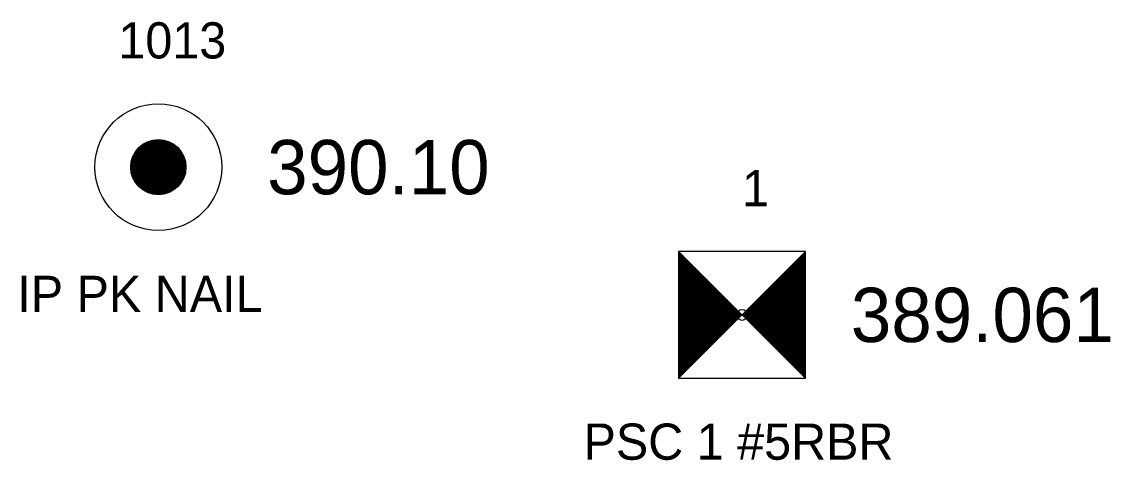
# Model space of a CAD drawing. Extents: x 2006517 to 2008868, y 1001613 to 1004633.
# Drawn here: x 2007086.65 to 2007116.66, y 1004406.67 to 1004418.78 of the extents above; entities that cross this region are included whole.
import ezdxf

# ---------------------------------------------------------------- set-up
doc = ezdxf.new("R2010")
doc.units = 0
for name, color, linetype in [('RD_EX_DV_Prop_txCode', 7, 'Continuous'), ('RD_EX_DV_PropPin', 7, 'Continuous'), ('RD_EX_TX_DV_Prop_ELEV', 7, 'Continuous'), ('RD_HC_Survey', 7, 'Continuous'), ('RD_HC_Survey_ELEV', 7, 'Continuous'), ('RD_HC_txCode', 7, 'Continuous'), ('RD_SMD_Locator', 7, 'Continuous')]:
    doc.layers.add(name, color=color, linetype=linetype)

msp = doc.modelspace()

# ---------------------------------------------------------------- linework, layer by layer
at = {"layer": 'RD_EX_DV_PropPin'}
for p, q in [((2007089.893, 1004414.215), (2007089.893, 1004415.317)), ((2007089.928, 1004414.184), (2007089.928, 1004415.348)), ((2007089.963, 1004414.156), (2007089.963, 1004415.376)), ((2007089.998, 1004414.131), (2007089.998, 1004415.4)), ((2007090.033, 1004414.11), (2007090.033, 1004415.422)), ((2007090.068, 1004414.09), (2007090.068, 1004415.442)), ((2007090.103, 1004414.073), (2007090.103, 1004415.459)), ((2007090.138, 1004414.058), (2007090.138, 1004415.473)), ((2007090.173, 1004414.045), (2007090.173, 1004415.486)), ((2007090.208, 1004414.034), (2007090.208, 1004415.497)), ((2007090.243, 1004414.025), (2007090.243, 1004415.507)), ((2007090.278, 1004414.018), (2007090.278, 1004415.514)), ((2007090.313, 1004414.012), (2007090.313, 1004415.52)), ((2007090.348, 1004414.008), (2007090.348, 1004415.524)), ((2007090.383, 1004414.006), (2007090.383, 1004415.526)), ((2007090.418, 1004414.005), (2007090.418, 1004415.527)), ((2007090.453, 1004414.006), (2007090.453, 1004415.526)), ((2007090.488, 1004414.008), (2007090.488, 1004415.524)), ((2007090.523, 1004414.012), (2007090.523, 1004415.52)), ((2007090.558, 1004414.018), (2007090.558, 1004415.514)), ((2007090.593, 1004414.025), (2007090.593, 1004415.507)), ((2007090.628, 1004414.034), (2007090.628, 1004415.497)), ((2007090.663, 1004414.045), (2007090.663, 1004415.486)), ((2007090.698, 1004414.058), (2007090.698, 1004415.473)), ((2007090.733, 1004414.073), (2007090.733, 1004415.459)), ((2007090.768, 1004414.09), (2007090.768, 1004415.442)), ((2007090.803, 1004414.11), (2007090.803, 1004415.422)), ((2007090.838, 1004414.131), (2007090.838, 1004415.4)), ((2007090.873, 1004414.156), (2007090.873, 1004415.376)), ((2007090.908, 1004414.184), (2007090.908, 1004415.348)), ((2007090.943, 1004414.215), (2007090.943, 1004415.317)), ((2007089.717, 1004414.468), (2007089.717, 1004415.064)), ((2007089.753, 1004414.396), (2007089.753, 1004415.135)), ((2007089.788, 1004414.339), (2007089.788, 1004415.192)), ((2007089.823, 1004414.292), (2007089.823, 1004415.24)), ((2007089.858, 1004414.251), (2007089.858, 1004415.281)), ((2007090.978, 1004414.251), (2007090.978, 1004415.281)), ((2007091.013, 1004414.292), (2007091.013, 1004415.24)), ((2007091.048, 1004414.339), (2007091.048, 1004415.192)), ((2007091.083, 1004414.396), (2007091.083, 1004415.135)), ((2007091.118, 1004414.468), (2007091.118, 1004415.064)), ((2007089.682, 1004414.57), (2007089.682, 1004414.962)), ((2007091.153, 1004414.57), (2007091.153, 1004414.962))]:
    msp.add_line(p, q, dxfattribs=at)
for radius in [1.75, 0.761]:
    msp.add_circle((2007090.418, 1004414.766), radius, dxfattribs=at)
at = {"layer": 'RD_HC_Survey'}
for p, q in [((2007104.762, 1004412.435), (2007108.261, 1004408.935)), ((2007108.261, 1004412.435), (2007104.762, 1004408.935)), ((2007104.786, 1004412.411), (2007104.786, 1004408.96)), ((2007104.811, 1004412.386), (2007104.811, 1004408.985)), ((2007104.836, 1004412.361), (2007104.836, 1004409.01)), ((2007104.861, 1004412.336), (2007104.861, 1004409.034)), ((2007104.885, 1004412.312), (2007104.885, 1004409.059)), ((2007108.138, 1004412.312), (2007108.138, 1004409.059)), ((2007108.162, 1004412.336), (2007108.162, 1004409.034)), ((2007108.187, 1004412.361), (2007108.187, 1004409.01)), ((2007108.212, 1004412.386), (2007108.212, 1004408.985)), ((2007108.237, 1004412.411), (2007108.237, 1004408.96)), ((2007104.91, 1004412.287), (2007104.91, 1004409.084)), ((2007104.935, 1004412.262), (2007104.935, 1004409.109)), ((2007104.959, 1004412.237), (2007104.959, 1004409.133)), ((2007104.984, 1004412.213), (2007104.984, 1004409.158)), ((2007105.009, 1004412.188), (2007105.009, 1004409.183)), ((2007105.034, 1004412.163), (2007105.034, 1004409.208)), ((2007105.058, 1004412.138), (2007105.058, 1004409.232)), ((2007105.083, 1004412.114), (2007105.083, 1004409.257)), ((2007105.108, 1004412.089), (2007105.108, 1004409.282)), ((2007105.133, 1004412.064), (2007105.133, 1004409.307)), ((2007105.157, 1004412.039), (2007105.157, 1004409.331)), ((2007105.182, 1004412.015), (2007105.182, 1004409.356)), ((2007107.841, 1004412.015), (2007107.841, 1004409.356)), ((2007107.866, 1004412.039), (2007107.866, 1004409.331)), ((2007107.89, 1004412.064), (2007107.89, 1004409.307)), ((2007107.915, 1004412.089), (2007107.915, 1004409.282)), ((2007107.94, 1004412.114), (2007107.94, 1004409.257)), ((2007107.965, 1004412.138), (2007107.965, 1004409.232)), ((2007107.989, 1004412.163), (2007107.989, 1004409.208)), ((2007108.014, 1004412.188), (2007108.014, 1004409.183)), ((2007108.039, 1004412.213), (2007108.039, 1004409.158)), ((2007108.064, 1004412.237), (2007108.064, 1004409.133)), ((2007108.088, 1004412.262), (2007108.088, 1004409.109)), ((2007108.113, 1004412.287), (2007108.113, 1004409.084)), ((2007105.207, 1004411.99), (2007105.207, 1004409.381)), ((2007105.232, 1004411.965), (2007105.232, 1004409.406)), ((2007105.256, 1004411.94), (2007105.256, 1004409.43)), ((2007105.281, 1004411.916), (2007105.281, 1004409.455)), ((2007105.306, 1004411.891), (2007105.306, 1004409.48)), ((2007105.331, 1004411.866), (2007105.331, 1004409.505)), ((2007105.355, 1004411.841), (2007105.355, 1004409.529)), ((2007105.38, 1004411.817), (2007105.38, 1004409.554)), ((2007105.405, 1004411.792), (2007105.405, 1004409.579)), ((2007105.43, 1004411.767), (2007105.43, 1004409.604)), ((2007105.454, 1004411.742), (2007105.454, 1004409.628)), ((2007105.479, 1004411.718), (2007105.479, 1004409.653)), ((2007105.504, 1004411.693), (2007105.504, 1004409.678)), ((2007107.519, 1004411.693), (2007107.519, 1004409.678)), ((2007107.544, 1004411.718), (2007107.544, 1004409.653)), ((2007107.569, 1004411.742), (2007107.569, 1004409.628)), ((2007107.593, 1004411.767), (2007107.593, 1004409.604)), ((2007107.618, 1004411.792), (2007107.618, 1004409.579)), ((2007107.643, 1004411.817), (2007107.643, 1004409.554)), ((2007107.668, 1004411.841), (2007107.668, 1004409.529)), ((2007107.692, 1004411.866), (2007107.692, 1004409.505)), ((2007107.717, 1004411.891), (2007107.717, 1004409.48)), ((2007107.742, 1004411.916), (2007107.742, 1004409.455)), ((2007107.767, 1004411.94), (2007107.767, 1004409.43)), ((2007107.791, 1004411.965), (2007107.791, 1004409.406)), ((2007107.816, 1004411.99), (2007107.816, 1004409.381)), ((2007105.529, 1004411.668), (2007105.529, 1004409.703)), ((2007105.553, 1004411.643), (2007105.553, 1004409.727)), ((2007105.578, 1004411.619), (2007105.578, 1004409.752)), ((2007105.603, 1004411.594), (2007105.603, 1004409.777)), ((2007105.628, 1004411.569), (2007105.628, 1004409.802)), ((2007105.652, 1004411.544), (2007105.652, 1004409.826)), ((2007105.677, 1004411.52), (2007105.677, 1004409.851)), ((2007105.702, 1004411.495), (2007105.702, 1004409.876)), ((2007105.727, 1004411.47), (2007105.727, 1004409.901)), ((2007105.751, 1004411.445), (2007105.751, 1004409.925)), ((2007105.776, 1004411.421), (2007105.776, 1004409.95)), ((2007105.801, 1004411.396), (2007105.801, 1004409.975)), ((2007107.222, 1004411.396), (2007107.222, 1004409.975)), ((2007107.247, 1004411.421), (2007107.247, 1004409.95)), ((2007107.272, 1004411.445), (2007107.272, 1004409.925)), ((2007107.296, 1004411.47), (2007107.296, 1004409.901)), ((2007107.321, 1004411.495), (2007107.321, 1004409.876)), ((2007107.346, 1004411.52), (2007107.346, 1004409.851)), ((2007107.371, 1004411.544), (2007107.371, 1004409.826)), ((2007107.395, 1004411.569), (2007107.395, 1004409.802)), ((2007107.42, 1004411.594), (2007107.42, 1004409.777)), ((2007107.445, 1004411.619), (2007107.445, 1004409.752)), ((2007107.47, 1004411.643), (2007107.47, 1004409.727)), ((2007107.494, 1004411.668), (2007107.494, 1004409.703)), ((2007105.826, 1004411.371), (2007105.826, 1004409.999)), ((2007105.85, 1004411.346), (2007105.85, 1004410.024)), ((2007105.875, 1004411.322), (2007105.875, 1004410.049)), ((2007105.9, 1004411.297), (2007105.9, 1004410.074)), ((2007105.925, 1004411.272), (2007105.925, 1004410.098)), ((2007105.949, 1004411.247), (2007105.949, 1004410.123)), ((2007105.974, 1004411.223), (2007105.974, 1004410.148)), ((2007105.999, 1004411.198), (2007105.999, 1004410.173)), ((2007106.024, 1004411.173), (2007106.024, 1004410.197)), ((2007106.048, 1004411.148), (2007106.048, 1004410.222)), ((2007106.073, 1004411.124), (2007106.073, 1004410.247)), ((2007106.098, 1004411.099), (2007106.098, 1004410.272)), ((2007106.925, 1004411.099), (2007106.925, 1004410.272)), ((2007106.95, 1004411.124), (2007106.95, 1004410.247)), ((2007106.975, 1004411.148), (2007106.975, 1004410.222)), ((2007106.999, 1004411.173), (2007106.999, 1004410.197)), ((2007107.024, 1004411.198), (2007107.024, 1004410.173)), ((2007107.049, 1004411.223), (2007107.049, 1004410.148)), ((2007107.074, 1004411.247), (2007107.074, 1004410.123)), ((2007107.098, 1004411.272), (2007107.098, 1004410.098)), ((2007107.123, 1004411.297), (2007107.123, 1004410.074)), ((2007107.148, 1004411.322), (2007107.148, 1004410.049)), ((2007107.173, 1004411.346), (2007107.173, 1004410.024)), ((2007107.197, 1004411.371), (2007107.197, 1004409.999)), ((2007106.123, 1004411.074), (2007106.123, 1004410.296)), ((2007106.147, 1004411.049), (2007106.147, 1004410.321)), ((2007106.172, 1004411.025), (2007106.172, 1004410.346)), ((2007106.197, 1004411), (2007106.197, 1004410.371)), ((2007106.222, 1004410.975), (2007106.222, 1004410.395)), ((2007106.246, 1004410.95), (2007106.246, 1004410.42)), ((2007106.271, 1004410.926), (2007106.271, 1004410.445)), ((2007106.296, 1004410.901), (2007106.296, 1004410.47)), ((2007106.321, 1004410.876), (2007106.321, 1004410.494)), ((2007106.345, 1004410.851), (2007106.345, 1004410.519)), ((2007106.37, 1004410.827), (2007106.37, 1004410.544)), ((2007106.395, 1004410.802), (2007106.395, 1004410.569)), ((2007106.628, 1004410.802), (2007106.628, 1004410.569)), ((2007106.653, 1004410.827), (2007106.653, 1004410.544)), ((2007106.678, 1004410.851), (2007106.678, 1004410.519)), ((2007106.702, 1004410.876), (2007106.702, 1004410.494)), ((2007106.727, 1004410.901), (2007106.727, 1004410.47)), ((2007106.752, 1004410.926), (2007106.752, 1004410.445)), ((2007106.777, 1004410.95), (2007106.777, 1004410.42)), ((2007106.801, 1004410.975), (2007106.801, 1004410.395)), ((2007106.826, 1004411), (2007106.826, 1004410.371)), ((2007106.851, 1004411.025), (2007106.851, 1004410.346)), ((2007106.876, 1004411.049), (2007106.876, 1004410.321)), ((2007106.9, 1004411.074), (2007106.9, 1004410.296)), ((2007106.42, 1004410.777), (2007106.42, 1004410.593)), ((2007106.444, 1004410.752), (2007106.444, 1004410.618)), ((2007106.469, 1004410.728), (2007106.469, 1004410.643)), ((2007106.494, 1004410.703), (2007106.494, 1004410.668)), ((2007106.529, 1004410.703), (2007106.529, 1004410.668)), ((2007106.554, 1004410.728), (2007106.554, 1004410.643)), ((2007106.579, 1004410.752), (2007106.579, 1004410.618)), ((2007106.603, 1004410.777), (2007106.603, 1004410.593))]:
    msp.add_line(p, q, dxfattribs=at)
msp.add_lwpolyline([(2007108.261, 1004412.435), (2007104.762, 1004412.435), (2007104.762, 1004408.935), (2007108.261, 1004408.935)], close=True, dxfattribs=at)
at = {"layer": 'RD_SMD_Locator'}
for centre in [(2007090.418, 1004414.766), (2007106.512, 1004410.685)]:
    msp.add_circle(centre, 0.15, dxfattribs=at)

# ---------------------------------------------------------------- texts
at = {"layer": 'RD_EX_DV_Prop_txCode'}
for s, p in [('1013', (2007089.315, 1004417.766)), ('IP PK NAIL', (2007086.528, 1004410.766))]:
    msp.add_text(s, height=1, dxfattribs=at).set_placement(p)
at = {"layer": 'RD_EX_TX_DV_Prop_ELEV'}
msp.add_text('390.10', height=1.5, dxfattribs=at).set_placement((2007093.418, 1004414.016))
at = {"layer": 'RD_HC_Survey_ELEV'}
msp.add_text('389.061', height=1.5, dxfattribs=at).set_placement((2007109.512, 1004409.935))
at = {"layer": 'RD_HC_txCode'}
for s, p in [('1', (2007106.512, 1004413.685)), ('PSC 1 #5RBR', (2007102.141, 1004406.685))]:
    msp.add_text(s, height=1, dxfattribs=at).set_placement(p)

doc.saveas('drawing.dxf')
